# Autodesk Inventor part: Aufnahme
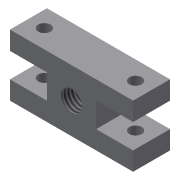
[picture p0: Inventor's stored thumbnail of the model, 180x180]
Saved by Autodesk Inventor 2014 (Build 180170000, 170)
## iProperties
Created: 2014-09
Part Number: Aufnahme
Material: Generisch
Document SubType Name: Modeling
Designer: e_dammj
Density: 1 g/cm^3
Appearance: Vorgabe
Author: e_dammj
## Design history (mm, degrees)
sketch "Skizze1"
  geometry: L1 (0, 0)-(0, 39.849); L2 (0, 0)-(-42.063, 0); L3 (0, 12.5)-(-25, 12.5); L4 (-25, 12.5)-(-25, 5); L5 (-25, 5)-(-10, 5); L6 (-10, 5)-(-10, 0); L7 (0, 0)-(0, -39.849); L8 (0, -12.5)-(-25, -12.5); L9 (-25, -12.5)-(-25, -5); L10 (-25, -5)-(-10, -5); L11 (-10, -5)-(-10, 0); L12 (0, 0)-(42.063, 0); L13 (0, 12.5)-(25, 12.5); L14 (25, 12.5)-(25, 5); L15 (25, 5)-(10, 5); L16 (10, 5)-(10, 0); L17 (0, -12.5)-(25, -12.5); L18 (25, -12.5)-(25, -5); L19 (25, -5)-(10, -5); L20 (10, -5)-(10, 0)
  constraints: 40 end point, 13 symmetric about line, 4 perpendicular, 4 point on line, 1 parallel, 1 vertical
  dimensions: "d0" = 50 diameter of L4 L1; "d1" = 10 diameter of L5 L2; "d2" = 20 diameter of L6 L1; "d3" = 25 diameter of L3 L2
extrude "Extrusion1" new body sketch "Skizze1" stored distance "d4" = 15; taper "d5" = 0 deg
sketch "Skizze2"
  geometry: 2 further points
  constraints: 1 coincident
hole "Bohrung1" sketch "Skizze2" at (0, 0) diameter "d6" = 8.376; stored, may be unused: countersink angle "d10" = 90 deg, drill point angle "d12" = 118 deg; dims "d7" = 6, "d8" = 4, "d9" = 2, "d11" = 8
sketch "Skizze3"
  geometry: L1 (0, 0)-(50, 0) reference; L2 (50, -15)-(0, -15) reference; L3 (25, 0)-(25, -15); 3 further points
  constraints: 2 end point, 2 midpoint, 1 symmetric about line
  dimensions: "d13" = 37 diameter of point (6.5, -7.5) L3
hole "Bohrung2" sketch "Skizze3" at (6.5, -7.5), (43.5, -7.5) diameter "d14" = 5; stored, may be unused: countersink angle "d18" = 90 deg, drill point angle "d20" = 118 deg; dims "d15" = 6, "d16" = 3.6, "d17" = 2, "d19" = 8
node "Volumenkörper1"
